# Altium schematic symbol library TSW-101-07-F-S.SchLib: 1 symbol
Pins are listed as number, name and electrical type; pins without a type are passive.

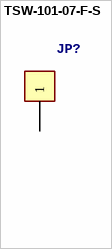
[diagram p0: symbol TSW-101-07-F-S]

## TSW-101-07-F-S
designator JP?
pins: 1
